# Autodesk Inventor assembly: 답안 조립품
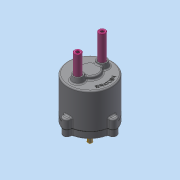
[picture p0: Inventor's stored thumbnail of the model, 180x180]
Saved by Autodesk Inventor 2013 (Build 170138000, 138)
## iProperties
Created: 2020-07
Part Number: 답안 조립품
Document SubType Name: Assembly
Designer: dgall
Mass: 1956.73 g
Surface Area: 1712.77 cm^2
Volume: 410.923 cm^3
Density: 4.7618 g/cm^3
Author: dgall
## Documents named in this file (14)
- C:\Users\dgall\Desktop\600706V1018\답안 조립품.iam
- C:\Users\dgall\Desktop\600706V1018\본체.ipt
- C:\Users\dgall\Desktop\600706V1018\개스킷.ipt
- C:\Users\dgall\Desktop\600706V1018\볼트 M5.ipt
- C:\Users\dgall\Desktop\600706V1018\오일 실.ipt
- C:\Users\dgall\Desktop\600706V1018\커버.ipt
- C:\Users\dgall\Desktop\600706V1018\멈춤링 22x1.2.ipt
- C:\Users\dgall\Desktop\600706V1018\메인 축.ipt
- C:\Users\dgall\Desktop\600706V1018\베어링 NA 4900.ipt
- C:\Users\dgall\Desktop\600706V1018\판캠.ipt
- C:\Users\dgall\Desktop\600706V1018\멈춤링 10x1.ipt
- C:\Users\dgall\Desktop\600706V1018\가변스프링-1.ipt
- C:\Users\dgall\Desktop\600706V1018\슬라이드 축.ipt
- C:\Users\dgall\Desktop\600706V1018\가변스프링-2.ipt
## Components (3 placed, 3 different names)
1. 개스킷:1
2. 가변스프링-1:1
3. 가변스프링-2:1
